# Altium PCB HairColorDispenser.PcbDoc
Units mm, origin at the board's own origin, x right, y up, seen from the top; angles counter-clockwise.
Board outline 93 x 77 mm, 2 copper layers (Top Layer, Bottom Layer), stack 0.325 mm thick; 86 components, 76 nets, 303 pads, 70 vias.
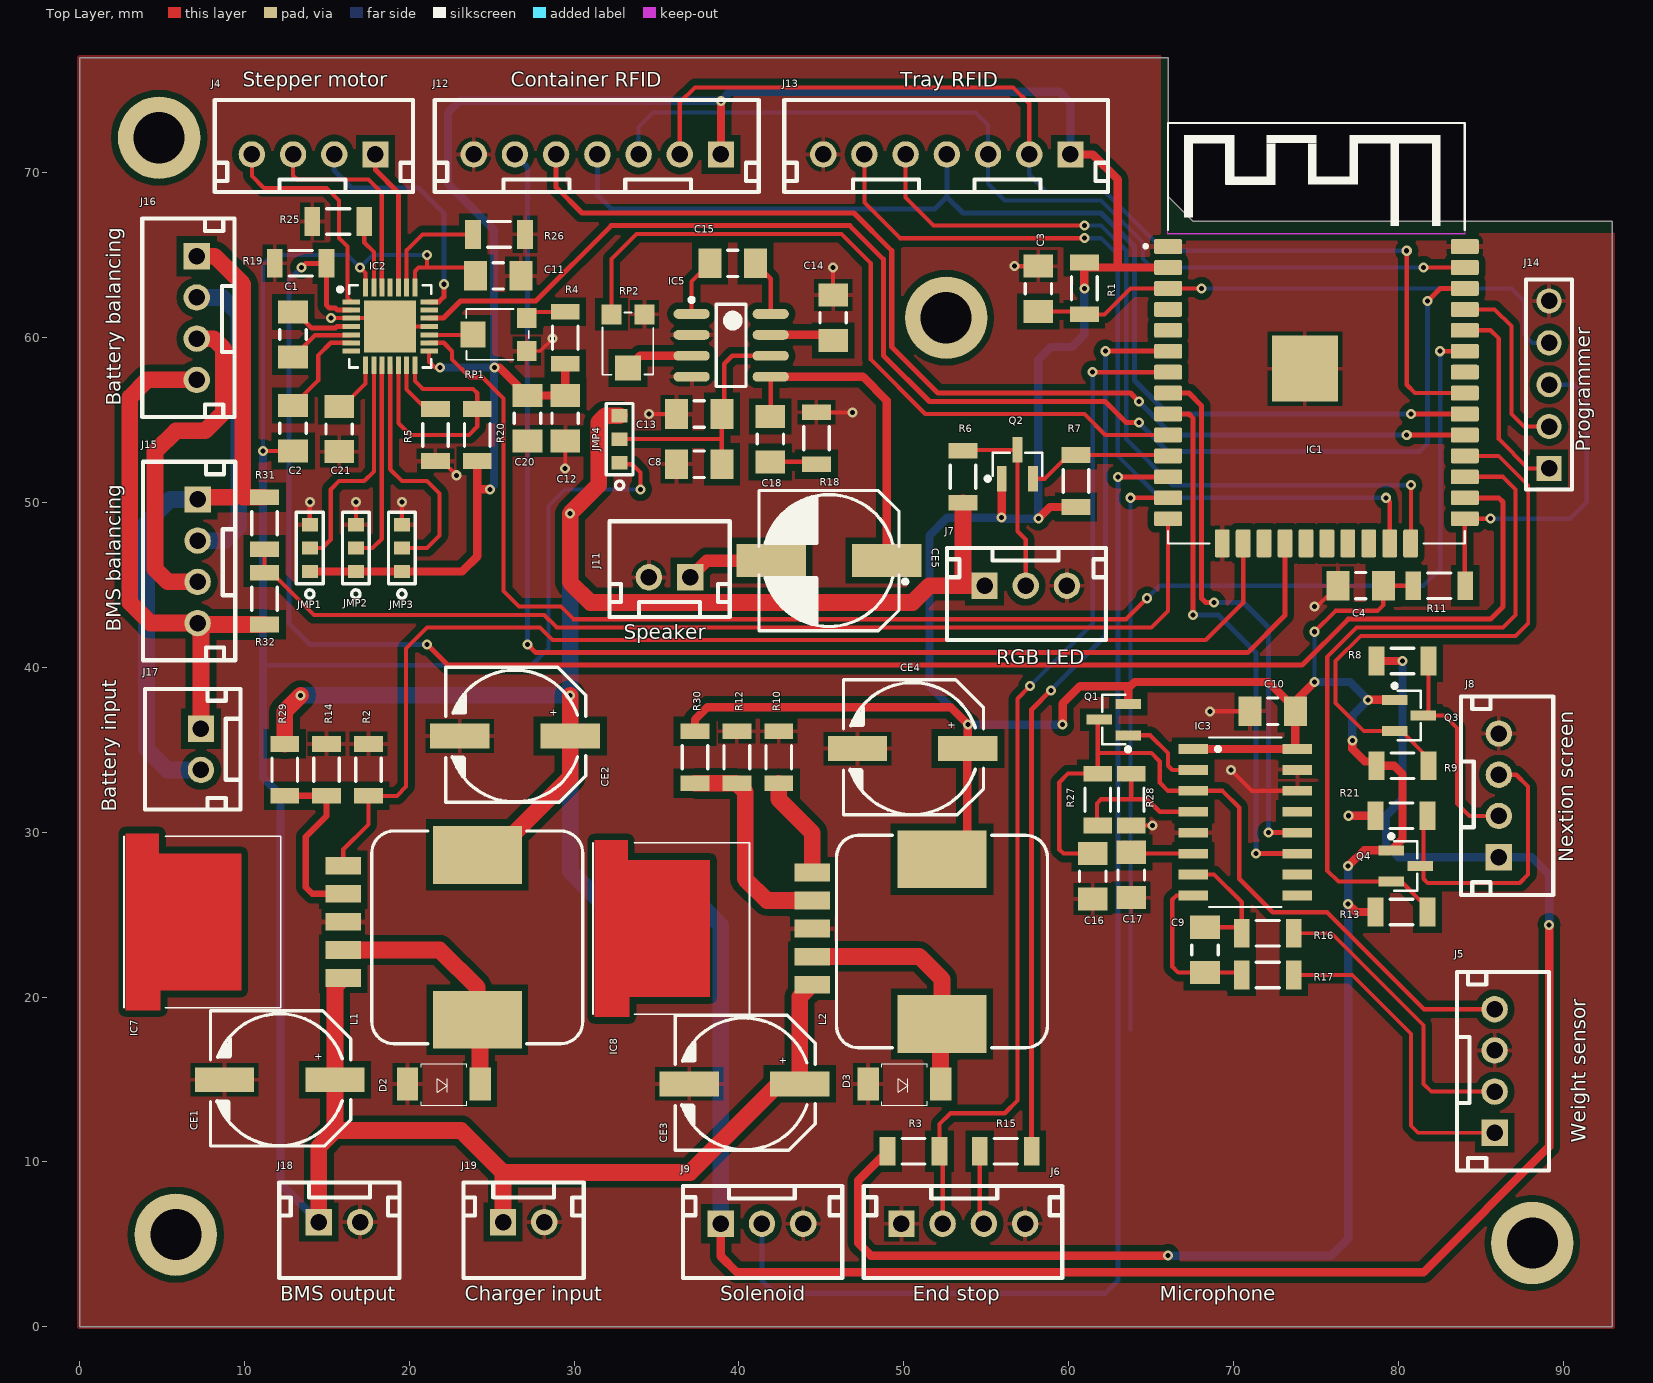
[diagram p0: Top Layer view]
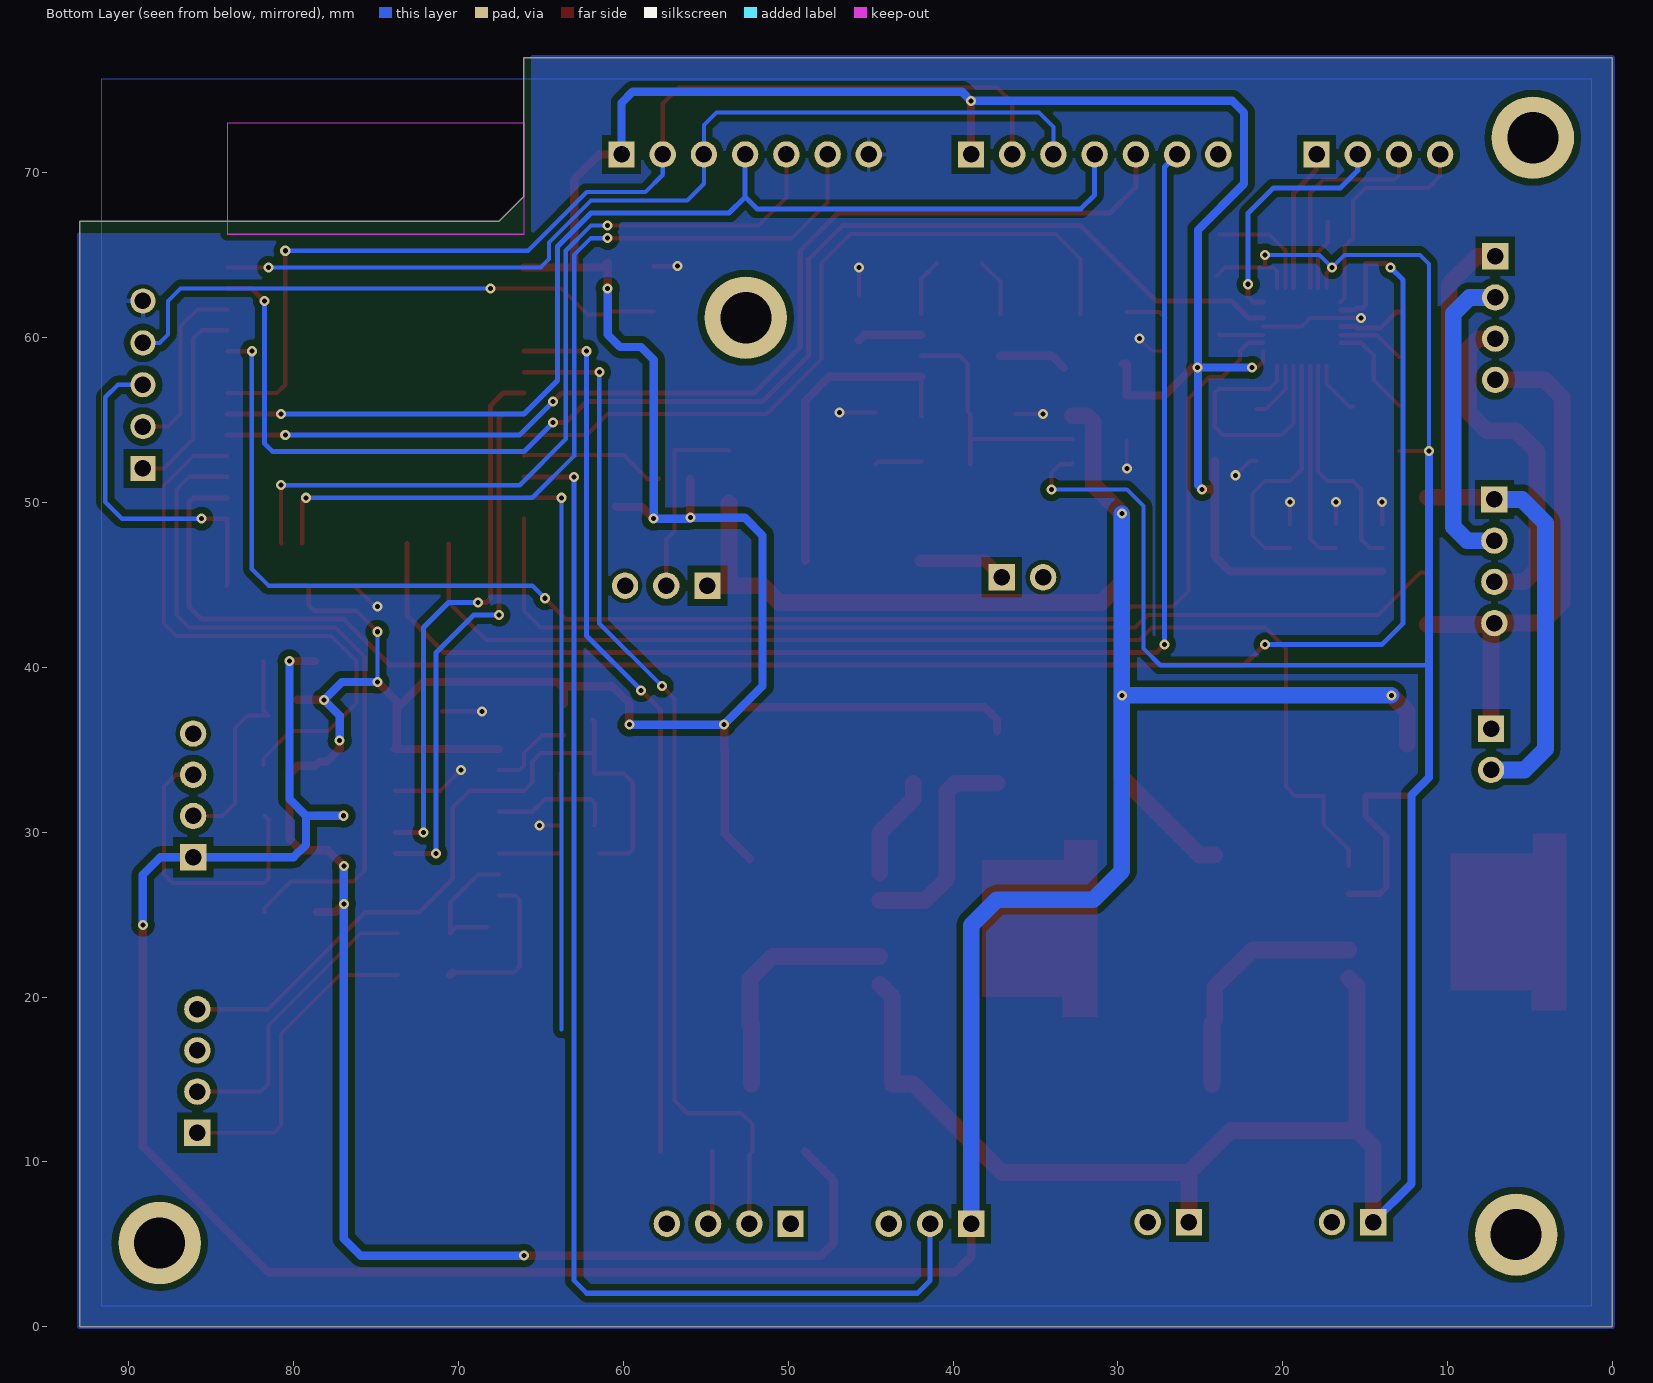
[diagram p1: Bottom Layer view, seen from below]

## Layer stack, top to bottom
Top Solder: solder mask 0.0102, Solder Resist, Dk 3.5
Top Layer: signal copper 0.0356
Dielectric 1: core 0.254, FR-4, Dk 4.2
Bottom Layer: signal copper 0.0356
Solder Side: solder mask 0.0102, Solder Resist, Dk 3.5

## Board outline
0,0 93,0 93,67.056 67.564,67.056 66.04,68.58 66.04,77 0,77

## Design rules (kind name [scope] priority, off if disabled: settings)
Clearance Clearance_1 [InComponent('IC2')] p1: gap=0.152 ignorepadtopadclearanceinfootprint=FALSE except(0: Arc-Hole Track-Hole SMDPad-Hole THPad-Hole Via-Hole Fill-Hole Poly-Hole Region-Hole Text-Hole)
Clearance "Clearance Poly" [InPoly] p2: gap=0.406 ignorepadtopadclearanceinfootprint=FALSE except(0: Arc-Hole Track-Hole SMDPad-Hole THPad-Hole Via-Hole Fill-Hole Poly-Hole Region-Hole Text-Hole)
Clearance [All] p3: gap=0.152 ignorepadtopadclearanceinfootprint=FALSE except(0: Arc-Hole Track-Hole SMDPad-Hole THPad-Hole Via-Hole Fill-Hole Poly-Hole Region-Hole Text-Hole)
DiffPairsRouting [All] p1: maxlimit=0.254 minlimit=0.254 mostfreqgap=0.254 toplayer_minwidth=0.254 toplayer_maxwidth=0.254 toplayer_prefwidth=0.254 bottomlayer_minwidth=0.254 bottomlayer_maxwidth=0.254 bottomlayer_prefwidth=0.254 maxuncoupledlength=12.7
HoleSize [All] p1: absolutevalues=TRUE maxlimit=12.7 minlimit=0.025 maxpercent=80.000 minpercent=20.000
MinimumSolderMaskSliver [All] p1: minsoldermaskwidth=0.025
PolygonConnect PolygonConnect_Via [IsVia] p1: connectstyle=Direct reliefconductorwidth=0.254 reliefentries=4 polygonreliefangle="90 Angle" airgapwidth=0.254
PolygonConnect [All] p2: connectstyle=Relief reliefconductorwidth=0.254 reliefentries=4 polygonreliefangle="90 Angle" airgapwidth=0.254
RoomDefinition HairColorDispenser [InComponentClass('HairColorDispenser')] p1: confinementstyle=ConfineIn formatcopy=TRUE lockcomponents=FALSE outline -598.755,-621.56 -547.955,-621.56 -547.955,-596.16 -598.755,-596.16
RoutingVias [All] p1: holewidth=0.254 width=0.508 viastyle="Through Hole" minholewidth=0.305 minwidth=0.61 maxholewidth=2.54 maxwidth=2.54
SilkToSilkClearance [All] p1: silktosilkclearance=0.127
SilkToSolderMaskClearance [IsPad] p1: minsilkscreentomaskgap=0.127 clearancetoexposedcopper=TRUE
SolderMaskExpansion [All] p1: expansion=0.102
Width [All] p1: maxlimit=2.032 minlimit=0.152 preferedwidth=0.254
25 further rules are at their usual default settings.

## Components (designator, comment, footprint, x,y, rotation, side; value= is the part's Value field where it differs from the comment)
C1 "100n" CAPC3216X18N 12.954,60.198 r270 top
C2 "100n" CAPC3216X18N 12.954,54.505 r270 top
C3 "100n" CAPC3216X18N 58.166,62.967 r270 top
C4 "100n" CAPC3216X18N 77.724,44.958 r0 top
C8 "100n" CAPC3216X18N 37.592,52.324 r0 top
C9 "100n" CAPC3216X18N 68.275,22.86 r90 top
C10 "100n" CAPC3216X18N 72.39,37.338 r0 top
C11 "100n" CAPC3216X18N 25.4,63.754 r180 top
C12 "100n" CAPC3216X18N 29.464,55.118 r90 top
C13 "10uF" CAPC3216X18N 37.592,55.372 r0 top
C14 "10uF" CAPC3216X18N 45.72,61.214 r270 top
C15 "10uF" CAPC3216X18N 39.624,64.516 r0 top
C16 "1uF" CAPC3216X18N 61.468,27.327 r90 top
C17 "1uF" CAPC3216X18N 63.804,27.41 r90 top
C18 "10p" CAPC3216X18N 41.91,53.848 r270 top
C20 "2u2" CAPC3216X18N 27.178,55.118 r90 top
C21 "220n" CAPC3216X18N 15.748,54.461 r90 top
CE1 "220uF" "220uF 35V" 12.144,14.961 r0 top
CE2 "220uF" "220uF 35V" 26.416,35.814 r0 top
CE3 "220uF" "220uF 35V" 40.338,14.707 r0 top
CE4 "220uF" "220uF 35V" 50.546,35.052 r0 top
CE5 "100u 25V" CAPAE800X550N 45.466,46.482 r180 top
D2 "1N5824" SOD128 22.098,14.732 r180 top
D3 "1N5824" SOD128 50.038,14.732 r180 top
IC1 "ESP32-WROOM-32" MODULE_ESP-WROOM-32 75.04,57.277 r0 top
IC2 "A4988" "28-QFN (5x5)" 18.846,60.684 r0 top
IC3 "HX711" SOP16 70.719,30.988 r0 top
IC5 "LM386" SOIC-8 39.534,59.541 r0 top
IC7 "LM2596 Adj" TO263-5 16.002,21.16 r90 top
IC8 "LM2596 Adj" TO263-5 44.447,20.756 r90 top
J4 "Stepper motor" B4B-HX-A 17.954,71.12 r180 top
J5 "Weight Sensor" B4B-HX-A 85.852,11.764 r90 top
J6 "QRD1114" B4B-HX-A 49.864,6.252 r0 top
J7 "WS2812B" B3B-HX-A 54.904,44.958 r0 top
J8 "Nextion" B4B-HX-A 86.106,28.488 r90 top
J9 "WS2812B" B3B-HX-A 38.902,6.252 r0 top
J11 "Speaker" B2B-XH-A 37.044,45.466 r180 top
J12 "RFID Container" B7B-HX-A 38.916,71.12 r180 top
J13 "RFID Tray" B7B-HX-A 60.118,71.12 r180 top
J14 "Programmer" HEADER1X5 89.154,55.88 r90 top
J15 "Balancing BMS" B4B-HX-A 7.162,50.19 r270 top
J16 "Balancing Battery" B4B-HX-A 7.112,64.944 r270 top
J17 "Battery Input" B2B-XH-A 7.366,36.282 r270 top
J18 "BMS Output" B2B-XH-A 14.518,6.35 r0 top
J19 "Charger Input" B2B-XH-A 25.694,6.35 r0 top
JMP1 "0R" JMP_SOLDER_3 13.97,47.244 r90 top
JMP2 "0R" JMP_SOLDER_3 16.764,47.244 r90 top
JMP3 "0R" JMP_SOLDER_3 19.558,47.244 r90 top
JMP4 "0R" JMP_SOLDER_3 32.766,53.848 r90 top
L1 "33uH 3A" "33uH 3A" 24.13,23.622 r90 top
L2 "33uH 3A" "33uH 3A" 52.324,23.368 r90 top
Q1 "MMBT4403" SOT95P230X126-3N 62.738,36.83 r180 top
Q2 "2N7002" SOT95P230X126-3N 56.896,52.324 r90 top
Q3 "2N7002" SOT95P230X126-3N 80.659,37.084 r0 top
Q4 "2N7002" SOT95P230X126-3N 80.456,27.953 r0 top
R1 "10K" "SMD 1206" 60.96,62.992 r90 top
R2 "10K" "SMD 1206" 17.526,33.782 r270 top
R3 "10K" "SMD 1206" 50.596,10.646 r180 top
R4 "10K" "SMD 1206" 29.464,59.995 r270 top
R5 "10K" "SMD 1206" 21.59,54.102 r90 top
R6 "10K" "SMD 1206" 53.594,51.562 r90 top
R7 "10K" "SMD 1206" 60.452,51.308 r270 top
R8 "10K" "SMD 1206" 80.264,40.386 r0 top
R9 "10K" "SMD 1206" 80.264,34.036 r180 top
R10 "10K" "SMD 1206" 42.418,34.544 r270 top
R11 "10K" "SMD 1206" 82.499,44.958 r0 top
R12 "1K" "SMD 1206" 39.878,34.544 r270 top
R13 "10K" "SMD 1206" 80.202,25.159 r180 top
R14 "1K" "SMD 1206" 14.986,33.782 r270 top
R15 "100R" "SMD 1206" 56.184,10.646 r180 top
R16 "100R" "SMD 1206" 72.085,23.876 r180 top
R17 "100R" "SMD 1206" 72.085,21.336 r180 top
R18 "100R" "SMD 1206" 44.704,53.899 r90 top
R19 "100K" "SMD 1206" 13.411,64.516 r180 top
R20 "100K" "SMD 1206" 24.13,54.102 r270 top
R21 "10K" "SMD 1206" 80.202,31.001 r0 top
R25 "0R05" "SMD 1206" 15.697,67.056 r180 top
R26 "0R05" "SMD 1206" 25.45,66.272 r0 top
R27 "20K" "SMD 1206" 61.772,31.982 r270 top
R28 "8.2K" "SMD 1206" 63.804,31.982 r90 top
R29 "3.09K" "SMD 1206" 12.446,33.782 r270 top
R30 "1.69K" "SMD 1206" 37.338,34.544 r270 top
R31 "33K" "SMD 1206" 11.226,48.746 r90 top
R32 "10K" "SMD 1206" 11.226,44.174 r90 top
RP1 "10K" "SMD POT" 27.126,59.198 r90 top
RP2 "10K" "SMD POT" 34.274,61.416 r180 top

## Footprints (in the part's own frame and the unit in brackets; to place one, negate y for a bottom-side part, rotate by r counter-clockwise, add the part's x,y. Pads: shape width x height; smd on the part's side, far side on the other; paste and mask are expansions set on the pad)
"28-QFN (5x5)" [mil] "28-VFQFN Exposed Pad (5x5)"
  rect 42x12 smd: 1(-93,59) 2(-93,39) 3(-93,20) 4(-93,0) 5(-93,-20) 6(-93,-39) 7(-93,-59) 15(93,-59) 16(93,-39) 17(93,-20) 18(93,0) 19(93,20) 20(93,39) 21(93,59)
  rect 12x42 smd: 8(-59,-93) 9(-39,-93) 10(-20,-93) 11(0,-93) 12(20,-93) 13(39,-93) 14(59,-93) 22(59,93) 23(39,93) 24(20,93) 25(0,93) 26(-20,93) 27(-39,93) 28(-59,93)
  rect 124x124 smd: 29(0,0)
  silkscreen extent -124,-98 98,98, body extent -98,-98 98,98, height 39
"33uH 3A" [mm] "Precision Wire Wound Inductor, 2-Leads, Body 12.5x12.5mm, IPC Low Density"
  rect 3.5x5.4 smd: 1(-5,0) 2(5,0)
  silkscreen extent -6.45,-6.4 6.45,6.4, body extent -6.25,-6.25 6.25,6.25, height 7.5
"220uF 35V" [mm] "Molded Capacitor, 2-Leads, Body 8x10mm, IPC Medium Density"
  rect 3.6x1.5 smd: 1(3.35,0.025) 2(-3.35,0.025)
  silkscreen extent -4.2,-4 4.3,4.2, body extent -4,-3.97 4,4.03, height 10
B2B-XH-A [mm]
  rect 1.6x1.6 hole 1: 1(0,0)
  round 1.6 hole 1: 2(2.5,0)
  silkscreen extent -2.4,-3.4 4.9,2.4, body extent -2.45,-3.38 4.95,2.37, height 7
B3B-HX-A [mm] "HEADER, TOP ENTRY, 3WAY, 2MM"
  rect 1.6x1.6 hole 1: 1(0,0)
  round 1.6 hole 1: 2(2.5,0) 3(5,0)
  silkscreen extent -2.29,-3.3 7.37,2.29, body extent -2.41,-3.38 7.49,2.37, height 7
B4B-HX-A [mm] "HEADER, TOP ENTRY, 4WAY, 2MM"
  rect 1.6x1.6 hole 1: 1(0,0)
  round 1.6 hole 1: 2(2.5,0) 3(5,0) 4(7.5,0)
  silkscreen extent -2.29,-3.3 9.75,2.29, body extent -2.44,-3.31 9.96,2.44, height 7
B7B-HX-A [mm] "HEADER, TOP ENTRY, 4WAY, 2MM"
  rect 1.6x1.6 hole 1: 1(0,0)
  round 1.6 hole 1: 2(2.5,0) 3(5,0) 4(7.5,0) 5(10,0) 6(12.5,0) 7(15,0)
  silkscreen extent -2.29,-3.3 17.37,2.29, body extent -2.4,-3.4 17.49,2.37, height 7
CAPAE800X550N [mm] "Molded Capacitor, 2-Leads, Body 8.3x8.3mm, IPC Medium Density"
  rect 4.2x2 smd: 1(-3.5,0) 2(3.5,0)
  silkscreen extent -4.75,-4.25 4.25,4.25, body extent -4.02,-3.99 3.98,4.01, height 5.5
CAPC3216X18N [mm] "Chip Capacitor, 2-Leads, Body 3.20x1.60mm, IPC Medium Density"
  rect 1.4x1.8 smd: 1(-1.375,0) 2(1.375,0)
  silkscreen extent -0.3,-0.8 0.3,0.8, body extent -1.68,-0.87 1.67,0.87, height 1.8
HEADER1X5 [mil]
  rect 60x60 hole 39.37: 1(-150,0)
  round 60 hole 39.37: 2(-50,0) 3(50,0) 4(150,0) 5(250,0)
  silkscreen extent -200,-55 302,55, body extent -200,-50 300,50, height 286
JMP_SOLDER_3 [mil] "3 X 0603"
  rect 32x38 smd: 1(-56,0) 2(0,0)
  rect 32x38 smd paste+0 mask+0: 3(56,0)
  silkscreen extent -120,-32 85,32, body extent -72,-19 16,19, height 24
MODULE_ESP-WROOM-32 [mm]
  rrect22% 1.7x0.9 smd: 1(-9,8.255) 2(-9,6.985) 3(-9,5.715) 4(-9,4.445) 5(-9,3.175) 6(-9,1.905) 7(-9,0.635) 8(-9,-0.635) 9(-9,-1.905) 10(-9,-3.175) 11(-9,-4.445) 12(-9,-5.715) 13(-9,-6.985) 14(-9,-8.255) 25(9,-8.255) 26(9,-6.985) 27(9,-5.715) 28(9,-4.445) 29(9,-3.175) 30(9,-1.905) 31(9,-0.635) 32(9,0.635) 33(9,1.905) 34(9,3.175) 35(9,4.445) 36(9,5.715) 37(9,6.985) 38(9,8.255)
  rect 4x4 smd: 1.1(-0.7,0.845)
  rrect22% 0.9x1.7 smd: 15(-5.715,-9.755) 16(-4.445,-9.755) 17(-3.175,-9.755) 18(-1.905,-9.755) 19(-0.635,-9.755) 20(0.635,-9.755) 21(1.905,-9.755) 22(3.175,-9.755) 23(4.445,-9.755) 24(5.715,-9.755)
  Keep-Out Layer region: 9,9.026 -9.026,9.026 -9.026,15.75 9,15.75
  Keep-Out Layer region: 9,9.012 -9.012,9.012 -9.012,15.75 9,15.75
  Keep-Out Layer region: 9,9.024 -9.024,9.024 -9.024,15.75 9,15.75
  silkscreen extent -10.46,-9.75 9,15.75, body extent -9.05,-9.8 9.02,15.74, height 3
"SMD 1206" [mm]
  rect 0.95x1.75 smd: 1(-1.575,0) 2(1.575,0)
  silkscreen extent -0.7,-0.77 0.7,0.77, body extent -1.6,-0.85 1.6,0.85, height 0.55
"SMD POT" [mm]
  rect 1.2x1.2 smd: 1(0,0) 3(2,0)
  rect 1.6x1.5 smd: 2(1,3.25)
  silkscreen extent -0.54,-0.12 2.55,3.66, body extent -0.54,-0.13 2.56,3.65, height 1.01
SOD128 [mm] "SOD128"
  rect 1.3x2 smd: 1(-2.2,0) 2(2.2,0)
  silkscreen extent -1.39,-1.22 1.38,1.3, body extent -2.45,-1.35 2.55,1.35, height 1.1
SOIC-8 [mm] "SOIC, 8-Leads, Body 5.0x4.0mm (max), Pitch 1.27mm, IPC Medium Density"
  oval 2.2x0.6 smd: 1(-2.4,1.905) 2(-2.4,0.635) 3(-2.4,-0.635) 4(-2.4,-1.905) 5(2.4,-1.905) 6(2.4,-0.635) 7(2.4,0.635) 8(2.4,1.905)
  silkscreen extent -2.52,-2.5 0.9,2.88, body extent -2,-2.5 2,2.5, height 1.75
SOP16 [mm] "SOIC, 8-Leads, Body 5.0x4.0mm (max), Pitch 1.27mm, IPC Medium Density"
  rect 1.8x0.59 smd: 1(-3.155,4.064) 2(-3.155,2.794) 3(-3.155,1.524) 4(-3.155,0.254) 5(-3.155,-1.016) 6(-3.155,-2.286) 7(-3.155,-3.556) 8(-3.155,-4.826) 9(3.155,-4.826) 10(3.155,-3.556) 11(3.155,-2.286) 12(3.155,-1.016) 13(3.155,0.254) 14(3.155,1.524) 15(3.155,2.794) 16(3.155,4.064)
  silkscreen extent -2.2,-5.53 2.2,4.77, body extent -3.96,-5.48 3.96,4.72, height 1.8
SOT95P230X126-3N [mm] "SOT23, 3-Leads, Body 3.0x2.5mm (max), Pitch 0.95mm, IPC Medium Density"
  rect 1.55x0.6 smd: 1(-0.875,0.95) 2(-0.875,-0.95) 3(0.875,0)
  silkscreen extent -1,-1.5 0.7,1.92, body extent -1.33,-1.48 1.23,1.44, height 1.07
TO263-5 [mm]
  rect 1.07x2.17 smd: 1(0,0) 2(1.7,0) 3(3.4,0) 4(5.1,0) 5(6.8,0)
  Top Layer region: -0.75,11.1 -0.75,6.2 7.55,6.2 7.55,11.2 8.75,11.2 8.75,13.2 -1.95,13.2 -1.95,11.1
  silkscreen extent -1.8,3.8 8.6,13.3, body extent -1.72,-0.82 8.5,13.22, height 4.38

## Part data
C1 C2: library part "100n 25V NP0", "CAP CER 0.1UF 25V NP0 1206", Manufacturer="Murata Electronics North America", Manufacturer Code=GRM31C5C1E104JA01L
C3 C4 C8 C9 C10 C11 C12: library part "100n 50V X7R", "CAP CER 0.1UF 50V X7R 1206", Manufacturer=KEMET, Manufacturer Code=C1206C104K5RAC7800
C13 C14 C15: library part "10uF 25V X7R", "CAP CER 10UF 25V X5R 1206", Manufacturer=KEMET, Manufacturer Code=C1206C106M3PACTU
C16 C17: library part "1uF 25V X7R", "CAP CER 1UF 25V X7R 1206", Manufacturer=KEMET, Manufacturer Code=C1206C105M3RACTU
C18: library part "10p 50V X7R", "CAP CER 10pF 50V NP0 1206", Manufacturer=KEMET, Manufacturer Code=C1206C100J5GACAUTO
C20: library part "2u2 50V X7R", "CAP CER 2.2UF 50V X7R 1206", Manufacturer=KEMET, Manufacturer Code=C1206C225K5RACAUTO
C21: library part "220n 50V X7R", "CAP CER 0.22UF 50V X7R 1206", Manufacturer=KEMET, Manufacturer Code=C1206C224K5RACTU
CE1 CE2 CE3 CE4: library part "220u 35V", "CAP ALUM 220UF 20% 35V SMD", Manufacturer=Nichicon, Manufacturer Code=UWT1V221MNL1GS
CE5: library part "100u 25V h=5.4mm", "CAPAE800X700 CASE E PANASONIC_EEEFK1E101P", Manufacturer=Nichicon, Manufacturer Code=UWX1E101MCL1GB
D2 D3: "DIODE SCHOTTKY 30V 5A MFLAT", Manufacturer="Toshiba Semiconductor and Storage", Manufacturer Code=CMS04(TE12L,Q,M)
IC1: "Bluetooth, WiFi Transceiver Module 2.4GHz ~ 2.5GHz Surface Mount", Manufacturer="Espressif Systems"
IC2: "IC MTR DRVR BIPOLAR 3-5.5V 28QFN", Manufacturer="Allegro MicroSystems", Manufacturer Code=A4988SETTR-T
IC3: "LOAD CELL AMP HX711"
IC5: "IC AMP AUDIO PWR .325W AB 8SOIC", Manufacturer="Texas Instruments", Manufacturer Code=LM386MX-1/NOPB
IC7 IC8: "IC REG MULT CONFG ADJ 3A D2PAK-5", Manufacturer="ON Semiconductor", Manufacturer Code=LM2596DSADJG
J4 J5 J6 J8 J15 J16: library part "JST 4-Pin 2.5mm B4B-XH-A", "CONN HEADER XH TOP 2POS 2.5MM", Manufacturer="JST Sales America Inc.", Manufacturer Code=B4B-XH-A(LF)(SN)
J7 J9: library part "JST 3-Pin 2.5mm B3B-XH-A", "CONN HEADER XH TOP 2POS 2.5MM", Manufacturer="JST Sales America Inc.", Manufacturer Code=B3B-XH-A(LF)(SN)
J11 J17 J18 J19: library part "JST 2-Pin 2.5mm B2B-XH-A", "CONN HEADER XH TOP 2POS 2.5MM", Manufacturer="JST Sales America Inc.", Manufacturer Code=B2B-XH-A(LF)(SN)
J12 J13: library part "JST 7-Pin 2.5mm B7B-XH-A", "CONN HEADER VERT 7POS 2.5MM", Manufacturer="JST Sales America Inc.", Manufacturer Code=B7B-XH-A(LF)(SN)
J14: library part "Header 1x5", "CONN HEADER VERT 5POS 2.54MM", Manufacturer="Harwin Inc.", Manufacturer Code=M20-9990546
JMP1 JMP2 JMP3 JMP4: library part "JMP-3 0R0 0603", "Solder Jumper 3x0603"
L1 L2: library part "IND 33u 3A", "FIXED IND 33UH 3A 60 MOHM SMD", Manufacturer="Bourns Inc.", Manufacturer Code=SRR1260-330M
Q1: "PNP 40V 600mA 200MHz 300mW SOT-23-3", Manufacturer="ON Semiconductor", Manufacturer Code=MMBT4403LT1G
Q2 Q3 Q4: "MOSFET N-CH 60V 115mA SOT-23", Manufacturer="ON Semiconductor"
R1 R2 R3 R4 R5 R6 R7 R8 R9 R10 R11 R13 R21 R32: library part "10K 1% 0.25W", "RES SMD 10K OHM 1% 1/4W 1206", Manufacturer=Yageo, Manufacturer Code=RC1206FR-0710KL
R12 R14: library part "1K 1% 0.25W", "RES SMD 1K OHM 1% 1/4W 1206", Manufacturer=Yageo, Manufacturer Code=RC1206FR-071KL
R15 R16 R17 R18: library part "100R 1% 0.25W", "RES SMD 100 OHM 1% 1/4W 1206", Manufacturer=Yageo, Manufacturer Code=RC1206FR-07100RL
R19 R20: library part "100K 1% 0.25W", "RES SMD 100K OHM 1% 1/4W 1206", Manufacturer=Yageo, Manufacturer Code=RC1206FR-07100KL
R25 R26: library part "0R05 0.5% 0.5W", "RES 50M OHM 0.5% 1/2W 1206", Manufacturer=Ohmite, Manufacturer Code=KDV12DR050ET
R27: library part "20K 1% 0.25W", "RES SMD 20K OHM 1% 1/4W 1206", Manufacturer=Yageo, Manufacturer Code=RC1206FR-0720KL
R28: library part "8K2 1% 0.25W", "RES SMD 8.2K OHM 5% 1/4W 1206", Manufacturer=Yageo, Manufacturer Code=RC1206JR-078K2L
R29: library part "3.09K 1% 0.25W", "RES SMD 3.09K OHM 1% 0.25W 1206", Manufacturer=Yageo, Manufacturer Code=RC1206FR-073K09L
R30: library part "1.69K 1% 0.25W_1", "RES SMD 1.69K OHM 1% 0.25W 1206", Manufacturer=Yageo, Manufacturer Code=RC1206FR-071K69L
R31: library part "33K 1% 0.25W", "RESISTOR, POWER, 1206, 1%, 33K", Manufacturer=Yageo, Manufacturer Code=RC1206FR-0733KL
RP1 RP2: library part "10k POT SMD", "TRIMMER 10K OHM 0.1W SMD", Manufacturer="Bourns Inc.", Manufacturer Code=TC33X-2-103E

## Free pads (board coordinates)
  round 5 hole 3.1: 0(4.826,72.136) 0(5.842,5.588) 0(52.578,61.214) 0(88.138,5.08)

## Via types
v1: diameter 0.61, hole 0.305, Top Layer to Bottom Layer, 70 vias

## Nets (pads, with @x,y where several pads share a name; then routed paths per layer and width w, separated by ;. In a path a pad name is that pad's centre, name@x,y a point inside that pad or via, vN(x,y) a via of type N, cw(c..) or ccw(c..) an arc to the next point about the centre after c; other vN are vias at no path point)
3V3: C4.2 C10.2 C12.2 C20.2 CE4.1 IC1.2 IC2.15 IC3.1 IC3.16 J12.1 J13.1 JMP1.1 JMP2.1 JMP3.1 L2.2 Q1.2 Q2.1 Q3.1 Q4.1 R1.2 R3.2 R4.2 R7.2 R9.2 R11.1 R13.2 R20.2 R30.1 | length 307.5
  Top Layer w0.254: IC2.15 21.208,58.548 21.565,58.191 v1(21.869,58.191) ; v1(74.93,42.164) 76.2,43.434 78.74,43.434 79.099,43.793 C4.2 R11.1
  Top Layer w0.508: JMP1.1 JMP2.1 JMP3.1 23.216,45.822 24.13,46.736 24.13,50.8 ; R20.2 24.13,50.8 ; v1(24.892,50.8) 24.13,50.8 ; v1(25.171,58.191) 25.48,58.191 C20.2 C12.2 R4.2 R4.2@29.718,58.42 ; R30.1 37.338,36.83 38.1,37.592 52.832,37.592 v1(53.896,36.528) CE4.1 53.848,35.125 53.848,29.892 L2.2 ; J12.1 v1(38.916,74.368) ; R3.2 47.244,8.869 47.244,5.08 48.006,4.318 v1(66.04,4.318) ; v1(55.946,49.088) Q2.1 ; v1(58.166,49.022) 58.877,49.733 R7.2 ; v1(59.642,36.528) 59.642,37.798 60.706,38.862 63.754,38.862 ; J13.1 61.468,71.12 62.992,69.596 62.992,64.262 ; v1(60.96,62.992) R1.2 61.265,64.262 62.992,64.262 ; Q1.2 63.613,38.721 63.754,38.862 ; IC1.2 62.992,64.262 ; IC3.1 IC3.16 ; C10.2@73.66,37.592 72.136,39.116 64.008,39.116 63.754,38.862 ; IC3.16@73.765,35.161 C10.2 73.765,37.951 v1(74.93,39.116) ; v1(76.962,25.654) 77.457,25.159 R13.2 ; v1(76.962,27.94) 77.925,28.903 Q4.1 80.264,29.586 80.264,33.528 79.756,34.036 R9.2 78.435,34.29 77.978,34.29 77.216,35.052 v1(77.216,35.56) ; v1(78.166,38.034) Q3.1
  Bottom Layer w0.254: v1(74.93,39.116) v1(74.93,42.164)
  Bottom Layer w0.508: v1(21.869,58.191) v1@25.146,58.191 ; v1(24.892,50.8) 25.146,51.054 v1@25.146,58.191 ; v1(25.171,58.191) v1@25.146,58.191 ; v1(59.642,36.528) v1(53.896,36.528) 51.562,38.862 51.562,48.006 52.644,49.088 v1(55.946,49.088) 56.012,49.022 v1(58.166,49.022) 58.166,58.674 58.928,59.436 60.198,59.436 60.96,60.198 v1(60.96,62.992) ; J13.1 60.118,74.248 59.436,74.93 39.478,74.93 v1(38.916,74.368) 23.06,74.368 22.352,73.66 22.352,69.342 25.146,66.548 v1@25.146,58.191 ; v1(66.04,4.318) 75.946,4.318 76.962,5.334 v1(76.962,25.654) v1(76.962,27.94) ; v1(74.93,39.116) 77.084,39.116 v1(78.166,38.034) 77.216,37.084 v1(77.216,35.56)
5V: CE2.1 J7.1 J8.1 J9.1 JMP4.3 L1.2 R6.1 R8.1 R21.1 R29.1 | length 225.5
  Top Layer w0.508: J9.1 38.902,4.278 39.878,3.302 81.534,3.302 89.154,10.922 v1(89.154,24.384) ; v1(76.975,31.001) R21.1 ; R8.1 v1(80.264,40.386)
  Top Layer w1.016: R29.1 12.446,37.338 v1(13.414,38.306) ; L1.2 25.066,28.622 29.766,33.322 CE2.1 v1(29.766,38.306) ; JMP4.3 31.902,55.27 31.496,54.864 31.496,51.054 v1(29.766,49.324) 29.766,45.164 30.988,43.942 50.546,43.942 51.562,44.958 53.594,44.958 ; R6.1 53.594,44.958 ; J7.1 53.594,44.958
  Bottom Layer w0.508: v1(76.975,31.001) 79.261,31.001 ; v1(80.264,40.386) 80.264,32.004 79.261,31.001 ; v1(89.154,24.384) 89.154,27.432 88.098,28.488 J8.1 80.01,28.488 79.261,29.237 79.261,31.001
  Bottom Layer w1.016: v1(13.414,38.306) v1(29.766,38.306) ; v1(29.766,49.324) v1(29.766,38.306) ; J9.1 38.902,24.344 37.338,25.908 31.496,25.908 29.766,27.638 v1(29.766,38.306)
12V: C2.2 C11.2 CE1.1 CE3.1 IC2.22 IC2.28 IC7.1 IC8.1 J18.1 J19.1 JMP4.1 | length 170.4
  Top Layer w0.254: v1(11.132,53.13) C2.2 ; v1(17.018,64.262) 17.347,63.933 IC2.28 ; IC2.22 20.345,64.033 20.574,64.262 21.082,64.262 ; v1(21.082,65.024) 21.082,64.262 ; C11.2 23.517,64.262 21.082,64.262 ; JMP4.1 32.868,52.324 33.528,52.324 34.036,51.816 v1(34.036,50.8)
  Top Layer w1.016: J18.1 14.518,10.922 15.494,11.898 ; IC7.1 15.494,20.652 CE1.1 15.494,11.898 ; J19.1 25.694,9.358 ; IC8.1 43.688,19.998 CE3.1 42.418,14.732 37.044,9.358 25.694,9.358 ; 15.494,11.898 23.154,11.898 25.694,9.358
  Bottom Layer w0.254: 11.132,40.132 27.432,40.132 28.448,41.148 28.448,49.784 29.464,50.8 v1(34.036,50.8) ; v1(11.132,53.13) 11.132,64.472 11.684,65.024 16.256,65.024 v1(17.018,64.262) 17.78,65.024 v1(21.082,65.024)
  Bottom Layer w0.508: v1(11.132,53.13) 11.132,40.132 11.132,33.318 12.192,32.258 12.192,8.676 J18.1
B1: J15.3 J16.3 | length 20.9
  Top Layer w1.016: J16.3 8.128,59.944 8.738,59.334 8.738,55.474 7.62,54.356 5.842,54.356 4.572,53.086 4.572,45.974 5.356,45.19 J15.3
B2: J15.2 J16.2 | length 18.7
  Bottom Layer w1.016: J16.2 8.676,62.444 9.652,61.468 9.652,48.514 8.828,47.69 J15.2
B+: J15.1 J16.1 J17.2 R31.2 | length 41.3
  Top Layer w1.016: J16.1 8.208,64.944 9.906,63.246 9.906,50.321 R31.2 ; J15.1 7.293,50.321 9.398,50.321
  Bottom Layer w1.016: J15.1 5.486,50.19 4.064,48.768 4.064,35.052 5.334,33.782 J17.2
B-: J15.4 J16.4 J17.1 R32.1 | length 32
  Top Layer w1.016: J16.4 4.104,57.444 3.048,56.388 3.048,43.942 4.3,42.69 J15.4 J15.4@7.253,42.599 ; J17.1 7.366,42.486 J15.4@7.253,42.599 ; R32.1 J15.4@7.253,42.599
EN: C3.2 IC1.3 J14.4 R1.1 | length 34.3
  Top Layer w0.254: C3.2 60.785,61.592 R1.1 62.179,61.417 63.754,62.992 IC1.3 v1(68.072,62.992)
  Bottom Layer w0.254: v1(68.072,62.992) 86.868,62.992 87.63,62.23 87.63,60.198 88.138,59.69 J14.4
GND: C3.1 C4.1 C8.1 C10.1 C11.1 C12.1 C13.1 C14.1 C16.1 C17.1 C20.1 C21.1 CE1.2 CE2.2 CE3.2 CE4.2 D2.2 D3.2 IC1.1 IC1.1.1 IC1.15 IC1.38 IC2.3 IC2.18 IC2.29 IC3.5 IC3.14 IC3.15 IC5.2 IC5.4 IC7.3 IC8.3 J5.3 J6.1 J6.4 J7.3 J8.4 J9.3 J11.2 J12.7 J13.7 J14.5 J18.2 J19.2 JMP1.3 JMP2.3 JMP3.3 R2.1 R5.1 R10.1 R12.1 R14.1 R18.2 R19.2 R25.2 R26.2 R28.1 RP1.1 RP2.1 | length 32.7
  Top Layer w0.203: RP1.1 27.956,59.198 v1(28.702,59.944) ; v1(29.464,52.07) C12.1
  Top Layer w0.254: JMP1.3 v1(13.97,50.038) ; v1(15.262,61.192) IC2.3 18.338,61.192 IC2.29 IC2.18 ; JMP2.3 v1(16.764,50.038) ; JMP3.3 v1(19.558,50.038) ; R5.1 21.99,52.527 v1(22.86,51.657) ; v1(34.544,55.372) C13.1 ; R18.2 v1(46.888,55.474) ; C14.1 v1(45.72,64.262) ; v1(56.722,64.342) C3.1 ; R28.1 v1(65.097,30.407) ; v1(68.58,37.338) C10.1 ; v1(69.85,33.782) 71.12,32.512 IC3.14 ; v1(74.93,43.688) 75.079,43.688 C4.1
IO0: IC1.25 J14.3 R11.2 | length 20.9
  Top Layer w0.254: R11.2 84.04,44.992 IC1.25 v1(85.598,49.022)
  Bottom Layer w0.254: v1(85.598,49.022) 90.424,49.022 91.44,50.038 91.44,56.388 90.678,57.15 J14.3
IO4: IC1.26 IC2.2 R19.1 | length 112.7
  Top Layer w0.305: v1(13.462,64.262) 13.716,64.516 R19.1 14.986,61.976 15.16,61.802 15.515,61.802 15.642,61.675 IC2.2 ; v1(21.082,41.402) 22.352,40.132 74.168,40.132 76.962,42.926 85.598,42.926 86.36,43.688 86.36,50.038 86.106,50.292 IC1.26
  Bottom Layer w0.305: v1(13.462,64.262) 12.7,63.5 12.7,42.672 13.97,41.402 v1(21.082,41.402)
IO12: IC1.14 R31.1 R32.2 | length 63.6
  Top Layer w0.254: R31.1 R32.2 11.655,45.749 14.224,43.18 28.194,43.18 28.956,42.418 65.024,42.418 66.04,43.434 IC1.14
IO13: IC1.16 IC7.5 R2.2 | length 71.9
  Top Layer w0.254: IC7.5 16.002,28.956 17.526,30.48 R2.2 19.253,32.207 19.812,32.766 19.812,41.148 21.082,42.418 27.94,42.418 28.702,41.656 68.326,41.656 70.595,43.925 IC1.16
IO14: IC1.13 | length 34.5
  Top Layer w0.254: v1(63.754,50.292) IC1.13
  Bottom Layer w0.254: 63.754,18.034 v1(63.754,50.292)
IO21: IC1.33 IC2.16 | length 91.4
  Top Layer w0.254: IC2.16 22.095,59.693 22.606,59.182 22.606,58.674 23.673,57.607 24.435,57.607 25.73,56.312 25.73,44.628 26.67,43.688 29.21,43.688 29.972,42.926 63.5,42.926 v1(64.77,44.196) ; v1(82.55,59.182) IC1.33
  Bottom Layer w0.254: v1(64.77,44.196) 65.532,44.958 81.534,44.958 82.55,45.974 v1(82.55,59.182)
IO22: IC1.36 IC2.19 | length 83.4
  Top Layer w0.305: IC2.19 22.076,61.192 23.114,62.23 27.686,62.23 32.258,66.802 46.736,66.802 48.768,64.77 48.768,58.928 51.562,56.134 62.23,56.134 63.5,54.864 v1(64.262,54.864) ; v1(81.788,62.23) 82.55,62.992 IC1.36
  Bottom Layer w0.305: v1(64.262,54.864) 66.04,53.086 81.28,53.086 81.788,53.594 v1(81.788,62.23)
IO25: IC1.10 RP2.3 | length 46.2
  Top Layer w0.254: RP2.3 32.274,64.786 33.782,66.294 46.228,66.294 48.006,64.516 48.006,58.674 51.308,55.372 60.96,55.372 62.23,54.102 IC1.10
IO26: IC1.11 Q2.2 R7.1 | length 8.8
  Top Layer w0.254: Q2.2 58.561,51.449 59.995,52.883 R7.1 65.989,52.883 IC1.11
IO27: IC1.12 J9.2 | length 77.5
  Top Layer w0.305: v1(62.992,51.562) IC1.12
  Bottom Layer w0.305: J9.2 41.402,2.794 42.164,2.032 62.23,2.032 62.992,2.794 v1(62.992,51.562)
IO32: IC1.8 IC3.12 | length 33
  Top Layer w0.305: IC1.8 67.31,56.642 68.072,55.88 68.072,44.196 68.326,43.942 v1(68.834,43.942) ; v1(72.136,29.972) IC3.12
  Bottom Layer w0.305: v1(68.834,43.942) 70.612,43.942 72.136,42.418 v1(72.136,29.972)
IO33: IC1.9 IC3.11 | length 33
  Top Layer w0.305: IC1.9 67.31,55.372 67.564,55.118 v1(67.564,43.18) ; v1(71.374,28.702) IC3.11
  Bottom Layer w0.305: v1(67.564,43.18) 69.088,43.18 71.374,40.894 v1(71.374,28.702)
IO34: IC1.6 R15.1 | length 54.2
  Top Layer w0.305: R15.1 57.759,37.439 v1(58.928,38.608) ; v1(62.23,59.182) IC1.6
  Bottom Layer w0.305: v1(58.928,38.608) 62.23,41.91 v1(62.23,59.182)
IO35: IC1.7 J6.2 R3.1 | length 62.1
  Top Layer w0.254: J6.2 52.364,10.453 R3.1 52.171,12.293 52.832,12.954 56.134,12.954 56.896,13.716 56.896,38.1 v1(57.658,38.862) ; v1(61.468,57.912) IC1.7
  Bottom Layer w0.254: v1(57.658,38.862) 61.468,42.672 v1(61.468,57.912)
MISO: IC1.31 J12.2 J13.2 | length 66.1
  Top Layer w0.254: J12.2 36.416,74.262 37.338,75.184 56.642,75.184 57.618,74.208 J13.2 ; v1(80.518,65.278) 80.518,57.15 81.026,56.642 IC1.31
  Bottom Layer w0.254: J13.2 57.618,69.89 58.674,68.834 62.23,68.834 65.786,65.278 v1(80.518,65.278)
MOSI: IC1.37 J12.3 J13.3 | length 58.7
  Top Layer w0.254: v1(81.534,64.262) IC1.37
  Bottom Layer w0.254: J12.3 33.916,72.778 34.798,73.66 54.356,73.66 55.118,72.898 J13.3 55.118,69.342 56.134,68.326 61.976,68.326 64.516,65.786 64.516,64.77 65.024,64.262 v1(81.534,64.262)
NetC1_1: C1.1 IC2.4 | length 4
  Top Layer w0.305: C1.1 13.103,61.573 14.094,60.582 15.515,60.582 15.616,60.684 IC2.4
NetC1_2: C1.2 IC2.5 | length 4.1
  Top Layer w0.254: C1.2 14.282,60.151 16.458,60.151 IC2.5
NetC2_1: C2.1 IC2.6 | length 6
  Top Layer w0.254: C2.1 14.478,57.404 14.478,58.928 15.243,59.693 IC2.6
NetC9_1: C9.1 IC3.8 R17.2 | length 9.9
  Top Layer w0.254: IC3.8 66.548,26.162 66.294,25.908 66.294,21.844 66.653,21.485 C9.1 R17.2@70.361,21.485
  Top Layer w0.508: R17.2@70.361,21.485 R17.2
NetC9_2: C9.2 IC3.7 R16.2 | length 7.9
  Top Layer w0.254: IC3.7 68.834,27.432 70.51,25.756 R16.2 70.151,24.235 C9.2
NetC14_2: C14.2 IC5.7 | length 3.9
  Top Layer w0.508: IC5.7 45.383,60.176 C14.2
NetC15_1: C15.1 IC5.1 | length 3.5
  Top Layer w0.254: IC5.1 37.134,63.401 C15.1
NetC15_2: C15.2 IC5.8 | length 3.5
  Top Layer w0.254: C15.2 41.934,63.581 IC5.8
NetC16_2: C16.2 IC3.3 J5.4 Q1.3 R27.1 | length 45.9
  Top Layer w0.254: C16.2 59.69,28.702 59.436,28.956 59.436,33.02 59.973,33.557 R27.1 61.772,34.798 ; Q1.3 61.772,36.739 61.772,34.798 ; J5.4 81.574,19.264 75.692,25.146 72.39,25.146 70.358,27.178 70.358,31.496 69.342,32.512 IC3.3 66.04,32.512 65.532,33.02 65.532,34.29 65.024,34.798 61.772,34.798
NetC17_2: C17.2 IC3.6 | length 3.8
  Top Layer w0.254: C17.2 63.887,28.702 IC3.6
NetC18_1: C18.1 CE5.1 IC5.5 | length 19.8
  Top Layer w0.254: C18.1 41.934,55.247 IC5.5
  Top Layer w0.508: IC5.5 47.52,57.636 48.966,56.19 CE5.1
NetC18_2: C18.2 R18.1 | length 2.9
  Top Layer w0.254: C18.2 44.555,52.473 R18.1
NetC21_2: C21.2 IC2.8 | length 3.3
  Top Layer w0.254: C21.2 15.958,55.836 17.347,57.225 IC2.8
NetCE5_2: CE5.2 J11.1 | length 5.3
  Top Layer w0.762: J11.1 38.06,46.482 CE5.2
NetD2_1: D2.1 IC7.2 L1.1 | length 15
  Top Layer w1.016: IC7.2 21.844,22.86 24.13,20.574 L1.1 24.298,18.454 D2.1
NetD3_1: D3.1 IC8.2 L2.1 | length 14.8
  Top Layer w1.016: IC8.2 50.95,22.456 52.324,21.082 L2.1 52.238,18.282 D3.1
NetIC2_1: IC2.1 J4.4 | length 13.7
  Top Layer w0.254: J4.4 10.454,69.81 11.176,69.088 14.986,69.088 15.748,68.326 15.748,66.04 16.256,65.532 16.256,62.41 IC2.1
NetIC2_9: IC2.9 JMP1.2 | length 14
  Top Layer w0.254: JMP1.2 14.732,47.244 15.24,47.752 15.24,50.8 15.748,51.308 17.272,51.308 17.855,51.891 IC2.9
NetIC2_10: IC2.10 JMP2.2 | length 12.3
  Top Layer w0.254: JMP2.2 17.78,47.244 18.338,47.802 IC2.10
NetIC2_11: IC2.11 JMP3.2 | length 15.1
  Top Layer w0.254: IC2.11 18.846,52.02 19.558,51.308 21.082,51.308 21.844,50.546 21.844,48.006 21.082,47.244 JMP3.2
NetIC2_12: IC2.12 IC2.14 R20.1 | length 15.9
  Top Layer w0.254: IC2.12 19.354,54.814 20.066,54.102 23.622,54.102 24.13,54.61 R20.1 24.13,56.642 23.876,56.896 20.828,56.896 20.345,57.379 IC2.14
NetIC2_13: IC2.13 R5.2 | length 3.7
  Top Layer w0.254: IC2.13 19.837,56.871 21.031,55.677 R5.2
NetIC2_17: IC2.17 RP1.2 | length 2.7
  Top Layer w0.254: IC2.17 23.854,60.176 RP1.2
NetIC2_21: IC2.21 J4.2 | length 14.8
  Top Layer w0.305: IC2.21 21.797,62.183 22.098,62.484 v1(22.098,63.246)
  Bottom Layer w0.305: J4.2 15.454,70.144 16.51,69.088 20.574,69.088 22.098,67.564 v1(22.098,63.246)
NetIC2_23: IC2.23 R26.1 | length 6.7
  Top Layer w0.254: IC2.23 19.837,65.303 20.806,66.272 R26.1
NetIC2_24: IC2.24 J4.1 | length 8.7
  Top Layer w0.305: J4.1 17.954,70.184 19.354,68.784 IC2.24
NetIC2_26: IC2.26 J4.3 | length 13.3
  Top Layer w0.254: J4.3@12.446,71.12 J4.3@12.75,70.816 ; J4.3 12.954,69.85 13.208,69.596 17.526,69.596 18.338,68.784 IC2.26
NetIC2_27: IC2.27 R25.1 | length 4.3
  Top Layer w0.254: R25.1 17.272,65.786 17.855,65.203 IC2.27
NetIC3_2: IC3.2 Q1.1 | length 5.3
  Top Layer w0.254: Q1.1 64.958,35.88 66.04,34.798 66.04,34.036 66.294,33.782 IC3.2
NetIC3_4: IC3.4 R27.2 R28.2 | length 9.2
  Top Layer w0.254: R27.2 61.722,30.457 61.722,31.75 61.976,32.004 63.804,32.004 ; R28.2 63.804,32.004 ; IC3.4 65.532,31.242 64.77,32.004 63.804,32.004
NetIC5_3: IC5.3 RP2.2 | length 4.2
  Top Layer w0.508: RP2.2 34.014,58.906 IC5.3
NetIC7_4: IC7.4 R14.2 R29.2 | length 11.1
  Top Layer w0.381: R29.2 R14.2 14.986,30.988 13.716,29.718 13.716,26.67 14.126,26.26 IC7.4
NetIC8_4: IC8.4 R12.2 R30.2 | length 13.1
  Top Layer w1.016: R30.2 R12.2 40.386,32.461 40.386,27.178 41.708,25.856 IC8.4
NetIC8_5: IC8.5 R10.2 | length 6.3
  Top Layer w1.016: R10.2 42.418,32.004 44.447,29.975 IC8.5
NetJ5_1: J5.1 R17.1 | length 19.4
  Top Layer w0.229: R17.1 77.216,21.336 80.772,17.78 80.772,12.192 81.2,11.764 J5.1
NetJ5_2: J5.2 R16.1 | length 18.3
  Top Layer w0.229: R16.1 75.946,23.876 81.534,18.288 81.534,14.732 82.002,14.264 J5.2
NetJ6_3: J6.3 R15.2 | length 4.5
  Top Layer w0.254: R15.2 54.609,6.507 J6.3
NetJ7_2: J7.2 Q2.3 R6.2 | length 11.8
  Top Layer w0.254: R6.2 53.656,53.199 Q2.3 56.896,48.26 57.404,47.752 J7.2
NetJ8_2: J8.2 Q3.3 R8.2 | length 13.2
  Top Layer w0.229: R8.2 81.839,37.389 Q3.3 82.804,37.084 83.566,36.322 83.566,31.75 84.328,30.988 J8.2
NetJ8_3: J8.3 Q4.3 R21.2 | length 18
  Top Layer w0.254: R21.2 81.534,30.758 81.534,27.178 81.788,26.924 87.376,26.924 87.884,27.432 87.884,32.766 87.162,33.488 J8.3
NetR4_1: R4.1 RP1.3 | length 2.5
  Top Layer w0.254: RP1.3 27.498,61.57 R4.1
RST1: IC1.29 J12.5 | length 66.8
  Top Layer w0.305: J12.5 28.916,69.128 30.48,67.564 46.99,67.564 49.276,65.278 49.276,59.436 52.07,56.642 63.754,56.642 v1(64.262,56.134) ; v1(80.518,54.102) IC1.29
  Bottom Layer w0.305: v1(64.262,56.134) 66.294,54.102 v1(80.518,54.102)
RST2: IC1.24 J13.5 | length 50.7
  Top Layer w0.254: J13.5 50.118,68.5 51.816,66.802 v1(60.96,66.802) ; IC1.24 80.772,47.539 v1(80.772,51.054)
  Bottom Layer w0.254: v1(60.96,66.802) 61.976,66.802 63.5,65.278 63.5,53.848 66.294,51.054 v1(80.772,51.054)
RX0: IC1.34 J14.1 | length 12.2
  Top Layer w0.254: IC1.34 85.598,60.452 86.106,59.944 86.106,53.848 87.884,52.07 J14.1
RX2: IC1.27 Q4.2 R13.1 | length 43.7
  Top Layer w0.254: R13.1 81.777,25.411 80.185,27.003 Q4.2 76.375,27.003 75.692,27.686 75.692,40.64 77.47,42.418 86.36,42.418 87.122,43.18 87.122,50.8 86.36,51.562 IC1.27
SCK: IC1.30 J12.4 J13.4 | length 68.5
  Top Layer w0.305: v1(80.772,55.372) IC1.30
  Bottom Layer w0.305: J12.4 31.416,68.66 32.258,67.818 51.896,67.818 52.618,68.54 ; J13.4 52.618,68.54 ; v1(80.772,55.372) 66.04,55.372 64.008,57.404 64.008,65.532 61.976,67.564 53.594,67.564 52.618,68.54
SS1: IC1.18 J12.6 | length 81.5
  Top Layer w0.305: v1(27.178,41.402) 27.686,40.894 70.866,40.894 73.135,43.163 IC1.18
  Bottom Layer w0.305: J12.6 27.178,70.358 v1(27.178,41.402)
SS2: IC1.23 J13.6 | length 52
  Top Layer w0.254: J13.6 47.618,68.206 49.784,66.04 v1(60.96,66.04) ; v1(79.248,50.292) 79.485,50.055 IC1.23
  Bottom Layer w0.254: v1(60.96,66.04) 61.976,66.04 62.992,65.024 62.992,52.832 65.532,50.292 v1(79.248,50.292)
TX0: IC1.35 J14.2 | length 11.2
  Top Layer w0.254: IC1.35 85.852,61.722 86.868,60.706 86.868,55.372 87.63,54.61 J14.2
TX2: IC1.28 Q3.2 R9.1 | length 35.6
  Top Layer w0.229: R9.1 81.839,34.493 80.198,36.134 Q3.2 77.912,36.134 76.2,37.846 76.2,40.386 77.724,41.91 87.122,41.91 87.884,42.672 87.884,51.054 86.106,52.832 IC1.28
VS: C8.2 C13.2 IC5.6 JMP4.2 | length 15.4
  Top Layer w0.254: JMP4.2 38.967,53.848 ; C8.2 38.967,53.848 ; IC5.6 39.602,58.906 39.116,58.42 39.116,55.521 C13.2 38.967,53.848
pads on no net: IC1.4 IC1.5 IC1.17 IC1.19 IC1.20 IC1.21 IC1.22 IC1.32 IC2.7 IC2.20 IC2.25 IC3.9 IC3.10 IC3.13

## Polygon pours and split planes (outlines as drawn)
GND on Bottom Layer "Bottom Layer-GND" (solid, remove dead copper, pour order 4): -0.127,0 -0.127,77 cw(c0,77) 0,77.127 65.532,77.127 cw(c65.532,77) 65.659,77 cw(c65.532,77) 65.582,76.883 65.582,66.344 92.906,66.344 cw(c93,66.258) 93.127,66.258 93.127,0 cw(c93,0) 93,-0.127 0,-0.127 cw(c0,0)
GND on Bottom Layer "Bottom-GND" (solid, shelved, pour order 0): 1.27,1.27 1.27,75.692 91.44,75.692 91.694,75.692 91.694,1.27 1.27,1.27
GND on Top Layer "Top Layer-GND" (solid, remove dead copper, pour order 2): -0.127,0 -0.127,77 cw(c0,77) 0,77.127 65.532,77.127 cw(c65.532,77) 65.659,77 cw(c65.532,77) 65.582,76.883 65.582,66.344 92.906,66.344 cw(c93,66.258) 93.127,66.258 93.127,0 cw(c93,0) 93,-0.127 0,-0.127 cw(c0,0)

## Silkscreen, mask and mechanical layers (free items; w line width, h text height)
Top Overlay:
  text "Stepper motor" at 9.906,74.93 h1.52
  text "Container RFID" at 26.162,74.93 h1.52
  text "Tray RFID" at 49.784,74.93 h1.52
  text "Battery balancing" at 2.794,55.88 h1.52 r90
  text "Programmer" at 91.948,53.086 h1.52 r90
  text "BMS balancing" at 2.794,42.164 h1.52 r90
  text "Speaker" at 33.02,41.402 h1.52
  text "RGB LED" at 55.626,39.878 h1.52
  text "Battery input" at 2.54,31.242 h1.52 r90
  text "Nextion screen" at 90.932,28.194 h1.52 r90
  text "Weight sensor" at 91.694,11.176 h1.52 r90
  text "BMS output" at 12.192,1.27 h1.52
  text "Charger input" at 23.368,1.27 h1.52
  text "Solenoid" at 38.862,1.27 h1.52
  text "End stop" at 50.546,1.27 h1.52
  text "Microphone" at 65.532,1.27 h1.52
Mechanical 1:
  the board outline again, w0.1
